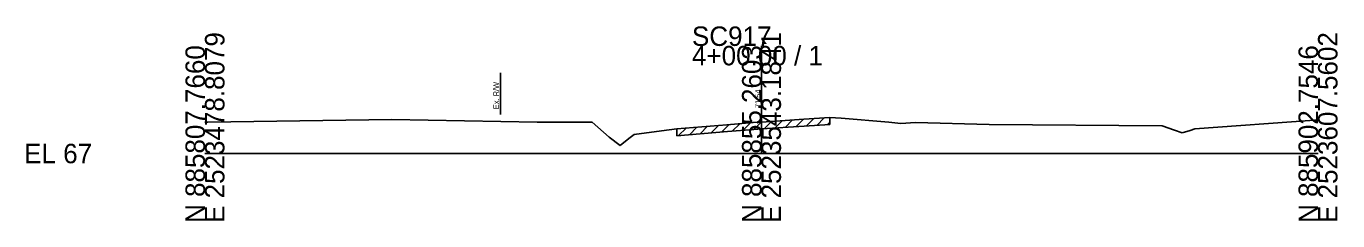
# Model space of a CAD drawing. Extents: x -26 to 218, y -10 to 12021.
# Drawn here: x -25.7 to 162.8, y 3990.3 to 4018.3 of the extents above; entities that cross this region are included whole.
import ezdxf

# ---------------------------------------------------------------- set-up
doc = ezdxf.new("R2010")
doc.units = 0
for name, color, linetype in [('RD_GPK_XS_Cell', 7, 'Continuous'), ('RD_XS_ExGround', 7, 'Continuous'), ('RD_XS_ExPaveRet', 7, 'Continuous'), ('RD_XS_ExRW', 7, 'Continuous'), ('RD_XS_TX_Elev_EX', 7, 'Continuous')]:
    doc.layers.add(name, color=color, linetype=linetype)

msp = doc.modelspace()

# ---------------------------------------------------------------- linework, layer by layer
at = {"layer": 'RD_GPK_XS_Cell'}
for p, q in [((80, 4000), (80, 4015.5)), ((0, 4000), (80, 4000)), ((80, 4000), (160, 4000))]:
    msp.add_line(p, q, dxfattribs=at)
at = {"layer": 'RD_XS_ExGround'}
for p, q in [((0, 4004.53), (0.43, 4004.53)), ((0.43, 4004.53), (26.86, 4004.89)), ((26.86, 4004.89), (47.73, 4004.51)), ((47.73, 4004.51), (55.64, 4004.52)), ((55.64, 4004.52), (58.11, 4002.38)), ((75.04, 4004.14), (78.81, 4004.46)), ((78.81, 4004.46), (80, 4004.54)), ((80, 4004.54), (86.07, 4004.93)), ((86.07, 4004.93), (89.82, 4005.17)), ((89.82, 4005.17), (91.45, 4005.09)), ((91.45, 4005.09), (98.3, 4004.54)), ((98.3, 4004.54), (100.02, 4004.31)), ((100.02, 4004.31), (102.15, 4004.46)), ((102.15, 4004.46), (112.72, 4004.2)), ((142.29, 4003.55), (159.49, 4004.82)), ((159.49, 4004.82), (160, 4004.86)), ((60.91, 4002.15), (61.7, 4002.76)), ((61.7, 4002.76), (65.62, 4003.28)), ((65.62, 4003.28), (67.85, 4003.56)), ((67.85, 4003.56), (75.04, 4004.14)), ((112.72, 4004.2), (137.6, 4003.98)), ((137.6, 4003.98), (139.38, 4003.37)), ((139.38, 4003.37), (140.48, 4002.97)), ((140.48, 4002.97), (141.64, 4003.3)), ((141.64, 4003.3), (142.29, 4003.55)), ((58.11, 4002.38), (59.69, 4001.15)), ((59.69, 4001.15), (60.91, 4002.15))]:
    msp.add_line(p, q, dxfattribs=at)
at = {"layer": 'RD_XS_ExPaveRet'}
for p, q in [((78.88, 4003.46), (79.95, 4004.53)), ((80.39, 4003.56), (81.46, 4004.63)), ((81.9, 4003.66), (82.97, 4004.73)), ((83.41, 4003.75), (84.48, 4004.83)), ((84.92, 4003.85), (85.99, 4004.92)), ((86.43, 4003.95), (87.5, 4005.02)), ((87.94, 4004.04), (89.01, 4005.12)), ((89.45, 4004.14), (89.82, 4004.51)), ((67.85, 4002.56), (75.12, 4003.15)), ((68.09, 4002.58), (69.18, 4003.67)), ((69.63, 4002.7), (70.72, 4003.79)), ((71.17, 4002.83), (72.26, 4003.92)), ((72.71, 4002.95), (73.8, 4004.04)), ((74.25, 4003.08), (75.34, 4004.17)), ((75.12, 4003.15), (78.89, 4003.46)), ((75.79, 4003.2), (76.88, 4004.3)), ((77.33, 4003.33), (78.43, 4004.43)), ((78.89, 4003.46), (80.06, 4003.54)), ((80.06, 4003.54), (86.14, 4003.93)), ((86.14, 4003.93), (89.82, 4004.17))]:
    msp.add_line(p, q, dxfattribs=at)
for points in [[(89.82, 4005.17), (89.82, 4004.17)], [(67.85, 4003.56), (67.85, 4002.56)]]:
    msp.add_lwpolyline(points, dxfattribs=at)
at = {"layer": 'RD_XS_ExRW'}
msp.add_line((42.5, 4011.61), (42.5, 4005.61), dxfattribs=at)

# ---------------------------------------------------------------- texts
at = {"layer": 'RD_GPK_XS_Cell'}
for s, p in [('SC917', (70, 4015.5)), ('4+00.00 / 1', (70, 4012.7)), ('EL 67', (-26, 3998.6))]:
    msp.add_text(s, height=2.8, dxfattribs=at).set_placement(p)
for s, p in [('E 2523478.8079', (2.8, 3990)), ('E 2523543.1841', (82.8, 3990)), ('E 2523607.5602', (162.8, 3990)), ('N 885807.7660', (0, 3990)), ('N 885855.2603', (80, 3990)), ('N 885902.7546', (160, 3990))]:
    msp.add_text(s, height=2.8, rotation=90, dxfattribs=at).set_placement(p)
at = {"layer": 'RD_XS_ExRW'}
msp.add_text('Ex. R/W ', height=0.8, rotation=90, dxfattribs=at).set_placement((42.25, 4006.39))
at = {"layer": 'RD_XS_TX_Elev_EX'}
msp.add_text('71.54', height=0.8, rotation=90, dxfattribs=at).set_placement((79.9, 4006.54))

doc.saveas('drawing.dxf')
